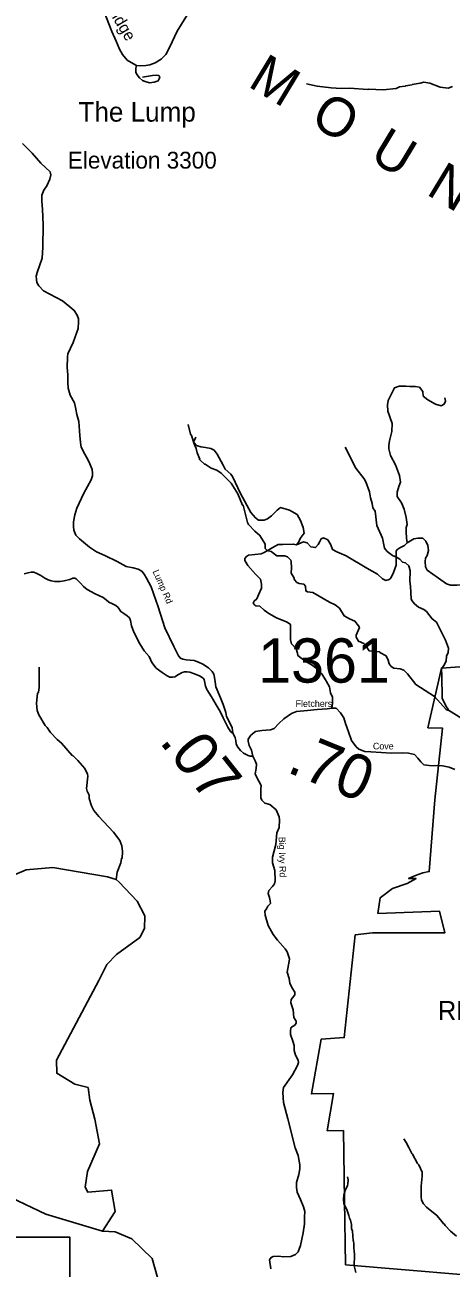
# Model space of a CAD drawing. Extents: x 1248224 to 1454986, y 825081 to 985870.
# Drawn here: x 1297355 to 1302167, y 914371 to 928409 of the extents above; entities that cross this region are included whole.
import ezdxf

# ---------------------------------------------------------------- set-up
doc = ezdxf.new("R2010")
doc.units = 0
for name, color, linetype in [('Exist Boundary Land Use Forest State Division NC Forest Resources', 7, 'Continuous'), ('Exist Boundary Land Use Forest State Division NC Forest Resources Label', 7, 'Continuous'), ('Exist Geographical Mountain Summit Elevation Number Label', 7, 'Continuous'), ('Exist Geographical Mountain Summit Label', 7, 'Continuous'), ('Exist Hydrographic Creek Single Shore', 7, 'Continuous'), ('Exist Hydrographic Misc Water Feature', 7, 'Continuous'), ('Exist Road Blue Ridge Parkway', 7, 'Continuous'), ('Exist Road Blue Ridge Parkway Label', 7, 'Continuous'), ('Exist Road Non-System Type 51', 7, 'Continuous'), ('Exist Road Secondary Mileage Hundredths English Label', 7, 'Continuous'), ('Exist Road Secondary Structure Standard Bridge Number Label', 7, 'Continuous'), ('Exist Road Secondary Type 10 Attributed', 7, 'Continuous'), ('Exist Road Secondary Type 41 Attributed', 7, 'Continuous'), ('Exist Road Secondary Type 51 Attributed', 7, 'Continuous'), ('Exist Road Secondary Type 51 Label', 7, 'Continuous'), ('Exist Road Secondary Type 51 Number Label', 7, 'Continuous')]:
    doc.layers.add(name, color=color, linetype=linetype)

msp = doc.modelspace()

# ---------------------------------------------------------------- linework, layer by layer
at = {"layer": 'Exist Boundary Land Use Forest State Division NC Forest Resources'}
for points in [[(1300766, 915922), (1300840, 916342), (1300590, 916339), (1300699, 916955), (1300961, 916975), (1301084, 918134), (1301278, 918158), (1302097, 918159), (1302034, 918403), (1301341, 918377), (1301367, 918554), (1301504, 918656), (1301669, 918714), (1301771, 918772), (1301687, 918771), (1301766, 918803), (1301846, 918835), (1301919, 918848), (1301983, 919658), (1302071, 920467), (1301905, 920473), (1302057, 921146), (1302520, 921181)], [(1302952, 914244), (1300975, 914409), (1300963, 915139), (1300950, 915924), (1300766, 915922)]]:
    msp.add_lwpolyline(points, dxfattribs=at)
at = {"layer": 'Exist Hydrographic Creek Single Shore'}
for points in [[(1298709, 918348), (1298622, 918514), (1298419, 918728), (1298384, 918759), (1298287, 918790), (1297672, 918894), (1297371, 918870), (1297093, 918751), (1296960, 918764), (1296796, 918859), (1296608, 919004), (1296160, 919449), (1296057, 919694), (1295662, 920236), (1295585, 920356), (1295434, 920469), (1295170, 920566), (1295036, 920562)], [(1298230, 914789), (1298373, 915010), (1298333, 915253), (1298066, 915229), (1298035, 915287), (1298062, 915463), (1298198, 915774), (1298143, 916052), (1298089, 916268), (1298069, 916410), (1297920, 916450), (1297715, 916572), (1297710, 916720), (1298191, 917620), (1298279, 917798), (1298390, 917914), (1298653, 918106), (1298706, 918207), (1298709, 918348)], [(1298230, 914789), (1297593, 914982), (1297197, 915168)], [(1299612, 911997), (1299233, 912165), (1299013, 912360), (1298949, 912506), (1298979, 912619), (1299029, 912692), (1299130, 913024), (1299049, 913268), (1299002, 913572), (1298954, 913904), (1298792, 914479), (1298562, 914702), (1298373, 914783), (1298230, 914789)]]:
    msp.add_lwpolyline(points, dxfattribs=at)
at = {"layer": 'Exist Hydrographic Misc Water Feature'}
for points in [[(1300533, 927744), (1300653, 927717), (1300812, 927696), (1300924, 927690), (1301021, 927693), (1301228, 927680), (1301234, 927684), (1301400, 927674), (1301545, 927689), (1301585, 927708), (1301649, 927715), (1301653, 927719), (1301726, 927731), (1301728, 927734), (1301818, 927749), (1301859, 927760), (1301926, 927750), (1302042, 927705), (1302133, 927695), (1302182, 927711)], [(1299200, 923898), (1299224, 923789), (1299235, 923773), (1299265, 923680), (1299289, 923624), (1299300, 923575), (1299331, 923507), (1299326, 923503), (1299385, 923445), (1299389, 923449), (1299456, 923405), (1299522, 923380), (1299569, 923347), (1299682, 923234), (1299757, 923112), (1299810, 922986), (1299818, 922986), (1299869, 922789), (1299881, 922769), (1299951, 922691)], [(1300970, 923642), (1301091, 923402), (1301186, 923285), (1301205, 923251), (1301247, 923135), (1301257, 923068), (1301274, 923006), (1301282, 922954), (1301308, 922917), (1301330, 922758), (1301391, 922613), (1301414, 922500), (1301445, 922464), (1301504, 922418), (1301552, 922399), (1301587, 922378), (1301618, 922341), (1301650, 922333), (1301691, 922300), (1301706, 922243), (1301700, 922128), (1301708, 922071), (1301717, 921929), (1301724, 921909), (1301752, 921872), (1301799, 921835), (1301860, 921808), (1301888, 921787), (1301954, 921702), (1302001, 921664), (1302102, 921461), (1302136, 921373), (1302135, 921321), (1302116, 921282), (1302111, 921225), (1302084, 921174), (1302057, 921137), (1302061, 921060), (1302065, 920808), (1302111, 920713), (1302134, 920682), (1302138, 920666)], [(1299951, 922691), (1300008, 922644), (1300064, 922552), (1300068, 922541), (1300069, 922495), (1300090, 922473), (1300136, 922464), (1300199, 922415), (1300287, 922412), (1300319, 922404), (1300356, 922363), (1300360, 922351), (1300366, 922279), (1300361, 922219), (1300392, 922170), (1300399, 922142), (1300426, 922113), (1300452, 922100), (1300504, 922093), (1300523, 922073), (1300526, 922018), (1300546, 922007), (1300606, 921999), (1300793, 921891), (1300859, 921859), (1300908, 921822), (1300958, 921736), (1301019, 921701), (1301081, 921677), (1301123, 921625), (1301131, 921604), (1301095, 921517), (1301094, 921497), (1301121, 921452), (1301181, 921423), (1301200, 921407), (1301241, 921342), (1301361, 921329), (1301363, 921324), (1301432, 921283), (1301455, 921235), (1301466, 921194), (1301489, 921166), (1301521, 921145), (1301592, 921139), (1301632, 921122), (1301675, 921081), (1301770, 920961), (1301928, 920861), (1301979, 920824), (1302110, 920677), (1302138, 920666)], [(1297516, 921156), (1297517, 920927), (1297508, 920876), (1297499, 920860), (1297484, 920752), (1297492, 920668), (1297511, 920619), (1297584, 920497), (1297608, 920477), (1297644, 920418), (1297718, 920340), (1297769, 920299), (1297888, 920160), (1297896, 920158), (1297951, 920104), (1298033, 920014), (1298061, 919949), (1298065, 919925), (1298049, 919786), (1298056, 919757), (1298079, 919713), (1298080, 919673), (1298106, 919592), (1298133, 919539), (1298191, 919470), (1298357, 919292), (1298425, 919198), (1298448, 919141), (1298458, 919077), (1298452, 918997), (1298444, 918997), (1298439, 918949), (1298398, 918842), (1298384, 918759)], [(1302931, 918253), (1302908, 918313), (1302920, 918470), (1302955, 918545), (1303014, 918951), (1303101, 919117), (1303092, 919425), (1303021, 919617), (1302822, 920015), (1302768, 920190), (1302589, 920388), (1302137, 920672)], [(1301633, 915830), (1301660, 915789), (1301691, 915733), (1301725, 915667), (1301732, 915659), (1301789, 915553), (1301801, 915537), (1301839, 915456), (1301841, 915408), (1301828, 915296), (1301827, 915176), (1301834, 915140), (1301855, 915098), (1301888, 915059), (1302007, 914967), (1302067, 914896), (1302082, 914873), (1302088, 914871), (1302100, 914853), (1302160, 914789), (1302227, 914733)], [(1300997, 915404), (1301004, 915368), (1301002, 915320), (1300998, 915304), (1300969, 915249), (1300955, 915194), (1300952, 915146), (1300956, 915102), (1300994, 915021), (1301012, 914964), (1301020, 914936), (1301031, 914912), (1301042, 914863), (1301044, 914819), (1301052, 914787), (1301061, 914683), (1301064, 914675), (1301068, 914647), (1301070, 914589), (1301074, 914574), (1301076, 914518), (1301073, 914399), (1301091, 914322)]]:
    msp.add_lwpolyline(points, dxfattribs=at)
at = {"layer": 'Exist Road Blue Ridge Parkway'}
for points in [[(1298614, 927951), (1298663, 927946), (1298719, 927949), (1298766, 927958), (1298825, 927980), (1298892, 928020), (1298946, 928074), (1298988, 928155), (1299074, 928337), (1299170, 928496), (1299275, 928640), (1299399, 928790), (1299600, 929013), (1299685, 929087), (1299786, 929161), (1299916, 929242), (1300015, 929291), (1300183, 929356), (1300282, 929397)], [(1298614, 927951), (1298556, 927982), (1298509, 928011), (1298455, 928076), (1298422, 928135), (1298384, 928225), (1298336, 928334), (1298224, 928624), (1298155, 928799), (1298101, 928907), (1298063, 928982), (1298024, 929039), (1297977, 929098), (1297930, 929135)]]:
    msp.add_lwpolyline(points, dxfattribs=at)
at = {"layer": 'Exist Road Non-System Type 51'}
for points in [[(1298614, 927951), (1298609, 927921), (1298606, 927899), (1298607, 927871), (1298624, 927843), (1298648, 927812), (1298682, 927780), (1298711, 927771), (1298762, 927756), (1298814, 927760), (1298858, 927778), (1298871, 927799), (1298877, 927823), (1298866, 927838), (1298836, 927840), (1298795, 927836), (1298750, 927829), (1298682, 927817)], [(1301669, 922562), (1301663, 922614), (1301658, 922683), (1301658, 922733), (1301671, 922768), (1301660, 922845), (1301638, 922939), (1301608, 923013), (1301559, 923085), (1301559, 923134), (1301578, 923198), (1301594, 923244), (1301583, 923319), (1301539, 923441), (1301484, 923548), (1301462, 923620), (1301462, 923658), (1301473, 923713), (1301498, 923818), (1301501, 923909), (1301454, 924046), (1301449, 924117), (1301457, 924166), (1301526, 924312), (1301581, 924328), (1301655, 924328), (1301702, 924326), (1301762, 924326), (1301809, 924317), (1301847, 924271), (1301853, 924218), (1301905, 924174), (1301990, 924128), (1302056, 924108), (1302087, 924125), (1302103, 924161), (1302095, 924196)], [(1299284, 923754), (1299261, 923705), (1299264, 923688), (1299293, 923659), (1299342, 923645), (1299394, 923636), (1299454, 923625), (1299491, 923607), (1299526, 923561), (1299592, 923437), (1299615, 923391), (1299678, 923337), (1299698, 923308), (1299790, 923118), (1299905, 922904), (1299957, 922843), (1299994, 922817), (1300057, 922817), (1300092, 922832), (1300138, 922866), (1300204, 922929), (1300239, 922958), (1300344, 922928), (1300427, 922881), (1300465, 922812), (1300498, 922735), (1300509, 922669), (1300463, 922609), (1300446, 922573), (1300422, 922538)], [(1300820, 920692), (1300826, 920746), (1300826, 920817), (1300804, 920867), (1300793, 920933), (1300760, 920994), (1300707, 921082), (1300644, 921145), (1300597, 921181), (1300518, 921225), (1300438, 921288), (1300432, 921315), (1300416, 921362), (1300366, 921420), (1300353, 921467), (1300355, 921558), (1300353, 921640), (1300314, 921665), (1300196, 921714), (1300108, 921764), (1300058, 921802), (1300006, 921844), (1299963, 921850), (1299952, 921858), (1299933, 921880), (1299944, 921902), (1299974, 921930), (1299993, 921974), (1300026, 922048), (1300026, 922095), (1300013, 922150), (1299960, 922207), (1299872, 922304), (1299837, 922361), (1299839, 922383), (1299856, 922408), (1299881, 922422), (1299952, 922430), (1300024, 922436), (1300057, 922450), (1300172, 922521), (1300216, 922540), (1300266, 922543), (1300384, 922546), (1300422, 922538), (1300447, 922549), (1300499, 922573), (1300543, 922560), (1300584, 922516), (1300637, 922507), (1300667, 922540), (1300681, 922568), (1300700, 922606), (1300727, 922617), (1300774, 922593), (1300810, 922538), (1300826, 922485), (1300876, 922458), (1300983, 922414), (1301215, 922274), (1301334, 922205), (1301391, 922155), (1301430, 922136), (1301466, 922147), (1301485, 922163), (1301515, 922227), (1301545, 922309), (1301548, 922411), (1301548, 922461), (1301554, 922480), (1301587, 922505), (1301639, 922532), (1301669, 922562)], [(1301669, 922562), (1301746, 922604), (1301790, 922612), (1301848, 922612), (1301883, 922579), (1301905, 922529), (1301911, 922474), (1301897, 922419), (1301878, 922389), (1301872, 922351), (1301878, 922290), (1301897, 922252), (1302024, 922161), (1302114, 922097), (1302161, 922084), (1302230, 922084), (1302293, 922086), (1302351, 922117), (1302442, 922152), (1302479, 922161), (1302490, 922156)]]:
    msp.add_lwpolyline(points, dxfattribs=at)
at = {"layer": 'Exist Road Secondary Structure Standard Bridge Number Label'}
msp.add_lwpolyline([(1294145, 914722), (1297861, 914722), (1297861, 913186), (1294145, 913186)], close=True, dxfattribs=at)
at = {"layer": 'Exist Road Secondary Type 10 Attributed'}
msp.add_lwpolyline([(1299929, 920150), (1299913, 920220), (1299887, 920272), (1299874, 920321), (1299874, 920344), (1299907, 920388), (1299959, 920432), (1300031, 920442), (1300128, 920450), (1300169, 920463), (1300221, 920519), (1300277, 920573), (1300365, 920635), (1300421, 920656), (1300547, 920668), (1300655, 920679), (1300766, 920687), (1300820, 920692), (1300869, 920692), (1300918, 920643), (1300956, 920584), (1300974, 920522), (1301007, 920427), (1301041, 920329), (1301095, 920259), (1301124, 920231), (1301194, 920203), (1301261, 920200), (1301495, 920187), (1301618, 920190), (1301685, 920187), (1301752, 920169), (1301790, 920131), (1301824, 920087), (1301860, 920054), (1301919, 920046), (1302070, 920041), (1302145, 920028), (1302207, 920000)], dxfattribs=at)
at = {"layer": 'Exist Road Secondary Type 41 Attributed'}
for points in [[(1297990, 923640), (1297983, 923692), (1297974, 923772), (1297966, 923876), (1297964, 923930), (1297942, 924010), (1297929, 924069), (1297914, 924143), (1297867, 924228), (1297845, 924308), (1297838, 924370), (1297839, 924456), (1297832, 924542), (1297834, 924655), (1297838, 924695), (1297900, 924821), (1297957, 924982), (1297961, 925056), (1297959, 925091), (1297945, 925132), (1297912, 925184), (1297864, 925224), (1297780, 925294), (1297564, 925404), (1297511, 925463), (1297488, 925499), (1297485, 925532), (1297483, 925572), (1297493, 925612), (1297549, 925776), (1297557, 925897), (1297562, 926152), (1297554, 926329), (1297545, 926416), (1297547, 926487), (1297568, 926544), (1297602, 926593), (1297635, 926665), (1297646, 926717), (1297639, 926750), (1297534, 926848), (1297438, 926961), (1297326, 927070)], [(1299705, 920409), (1299699, 920438), (1299694, 920476), (1299630, 920600), (1299623, 920644), (1299595, 920736), (1299562, 920812), (1299509, 920933), (1299502, 920990), (1299497, 921039), (1299487, 921079), (1299469, 921109), (1299426, 921149), (1299362, 921190), (1299313, 921214), (1299267, 921232), (1299177, 921240), (1299137, 921247), (1299111, 921260), (1299088, 921284), (1299038, 921390), (1298936, 921602), (1298858, 921837), (1298779, 922062), (1298726, 922162), (1298700, 922206), (1298675, 922239), (1298632, 922265), (1298577, 922280), (1298497, 922292), (1298397, 922351), (1298256, 922419), (1298165, 922458), (1298083, 922512), (1297973, 922605), (1297931, 922647), (1297907, 922704), (1297902, 922746), (1297905, 922796), (1297919, 922876), (1297940, 922953), (1298021, 923123), (1298104, 923272), (1298118, 923318), (1298118, 923349), (1298113, 923390), (1298087, 923454), (1298070, 923493), (1298030, 923560), (1297990, 923640)], [(1299705, 920409), (1299675, 920432), (1299647, 920480), (1299594, 920584), (1299560, 920658), (1299514, 920732), (1299461, 920820), (1299410, 920905), (1299394, 920942), (1299380, 921016), (1299369, 921032), (1299327, 921058), (1299258, 921087), (1299218, 921100), (1299187, 921104), (1299157, 921104), (1299130, 921096), (1299088, 921074), (1299048, 921047), (1299025, 921043), (1298993, 921045), (1298960, 921060), (1298905, 921096), (1298838, 921147), (1298789, 921210), (1298758, 921278), (1298702, 921342), (1298654, 921419), (1298584, 921552), (1298560, 921625), (1298547, 921683), (1298535, 921713), (1298511, 921735), (1298470, 921761), (1298437, 921784), (1298406, 921831), (1298381, 921853), (1298342, 921870), (1298303, 921892), (1298273, 921918), (1298239, 921943), (1298150, 921984), (1298059, 922034), (1298016, 922069), (1297982, 922107), (1297934, 922153), (1297918, 922162), (1297895, 922160), (1297861, 922147), (1297798, 922133), (1297753, 922125), (1297694, 922123), (1297652, 922130), (1297617, 922141), (1297580, 922161), (1297536, 922191), (1297490, 922215), (1297457, 922228), (1297427, 922228), (1297391, 922223), (1297348, 922209)], [(1299929, 920150), (1299899, 920150), (1299875, 920159), (1299824, 920184), (1299789, 920214), (1299758, 920253), (1299740, 920288), (1299735, 920330), (1299730, 920360), (1299705, 920409)]]:
    msp.add_lwpolyline(points, dxfattribs=at)
at = {"layer": 'Exist Road Secondary Type 51 Attributed'}
msp.add_lwpolyline([(1300132, 914365), (1300115, 914466), (1300135, 914491), (1300159, 914503), (1300214, 914508), (1300280, 914500), (1300357, 914503), (1300411, 914525), (1300441, 914557), (1300465, 914628), (1300495, 914771), (1300512, 914872), (1300512, 914949), (1300515, 915010), (1300500, 915062), (1300465, 915147), (1300428, 915229), (1300423, 915281), (1300423, 915338), (1300446, 915429), (1300460, 915491), (1300460, 915538), (1300453, 915580), (1300441, 915644), (1300406, 915730), (1300325, 916057), (1300273, 916243), (1300268, 916356), (1300275, 916410), (1300377, 916555), (1300433, 916661), (1300443, 916693), (1300441, 916720), (1300409, 916775), (1300394, 916829), (1300394, 916886), (1300379, 916935), (1300352, 917009), (1300352, 917046), (1300357, 917086), (1300364, 917093), (1300401, 917113), (1300419, 917138), (1300416, 917161), (1300391, 917203), (1300384, 917287), (1300357, 917368), (1300362, 917403), (1300377, 917423), (1300401, 917457), (1300401, 917489), (1300369, 917541), (1300345, 917588), (1300337, 917642), (1300315, 917714), (1300340, 917838), (1300342, 917865), (1300317, 917943), (1300293, 917975), (1300236, 918039), (1300206, 918073), (1300157, 918138), (1300100, 918239), (1300066, 918355), (1300063, 918402), (1300083, 918429), (1300098, 918460), (1300127, 918489), (1300125, 918519), (1300115, 918558), (1300103, 918603), (1300108, 918635), (1300150, 918679), (1300172, 918712), (1300182, 918746), (1300177, 918860), (1300150, 918949), (1300152, 919013), (1300187, 919156), (1300201, 919286), (1300226, 919345), (1300231, 919434), (1300226, 919468), (1300191, 919547), (1300122, 919607), (1300063, 919621), (1300029, 919656), (1300019, 919681), (1300019, 919779), (1300024, 919819), (1299969, 919918), (1299955, 919952), (1299965, 920011), (1299969, 920061), (1299955, 920100), (1299929, 920150)], dxfattribs=at)

# ---------------------------------------------------------------- texts
at = {"layer": 'Exist Boundary Land Use Forest State Division NC Forest Resources Label'}
msp.add_text('RENDEZVOUS MOUNTAIN STATE FOREST', height=215, dxfattribs=at).set_placement((1302018, 917172))
at = {"layer": 'Exist Geographical Mountain Summit Elevation Number Label'}
msp.add_text('Elevation 3300', height=190, dxfattribs=at).set_placement((1297840, 926786))
at = {"layer": 'Exist Geographical Mountain Summit Label'}
msp.add_text('M  O  U  N  T  A  I  N', height=440, rotation=328.8202, dxfattribs=at).set_placement((1299859, 927722))
msp.add_text('The Lump', height=220, dxfattribs=at).set_placement((1297960, 927316))
at = {"layer": 'Exist Road Blue Ridge Parkway Label'}
msp.add_text('Ridge', height=131.2, rotation=300.942, dxfattribs=at).set_placement((1298268, 928606))
at = {"layer": 'Exist Road Secondary Mileage Hundredths English Label'}
for s, rotation, p in [('.07', 308.4313, (1298863, 920315)), ('.70', 337.8174, (1300298, 919977))]:
    msp.add_text(s, height=500, rotation=rotation, dxfattribs=at).set_placement(p)
at = {"layer": 'Exist Road Secondary Type 51 Label'}
for s, rotation, p in [('Lump Rd', 293.7807, (1298795, 922237)), ('Big Ivy Rd', 271.4285, (1300220, 919240))]:
    msp.add_text(s, height=75, rotation=rotation, dxfattribs=at).set_placement(p)
for s, p in [('Fletchers', (1300411, 920708)), ('Cove', (1301284, 920228))]:
    msp.add_text(s, height=75, dxfattribs=at).set_placement(p)
at = {"layer": 'Exist Road Secondary Type 51 Number Label'}
msp.add_text('1361', height=500, dxfattribs=at).set_placement((1299988, 920982))

doc.saveas('drawing.dxf')
